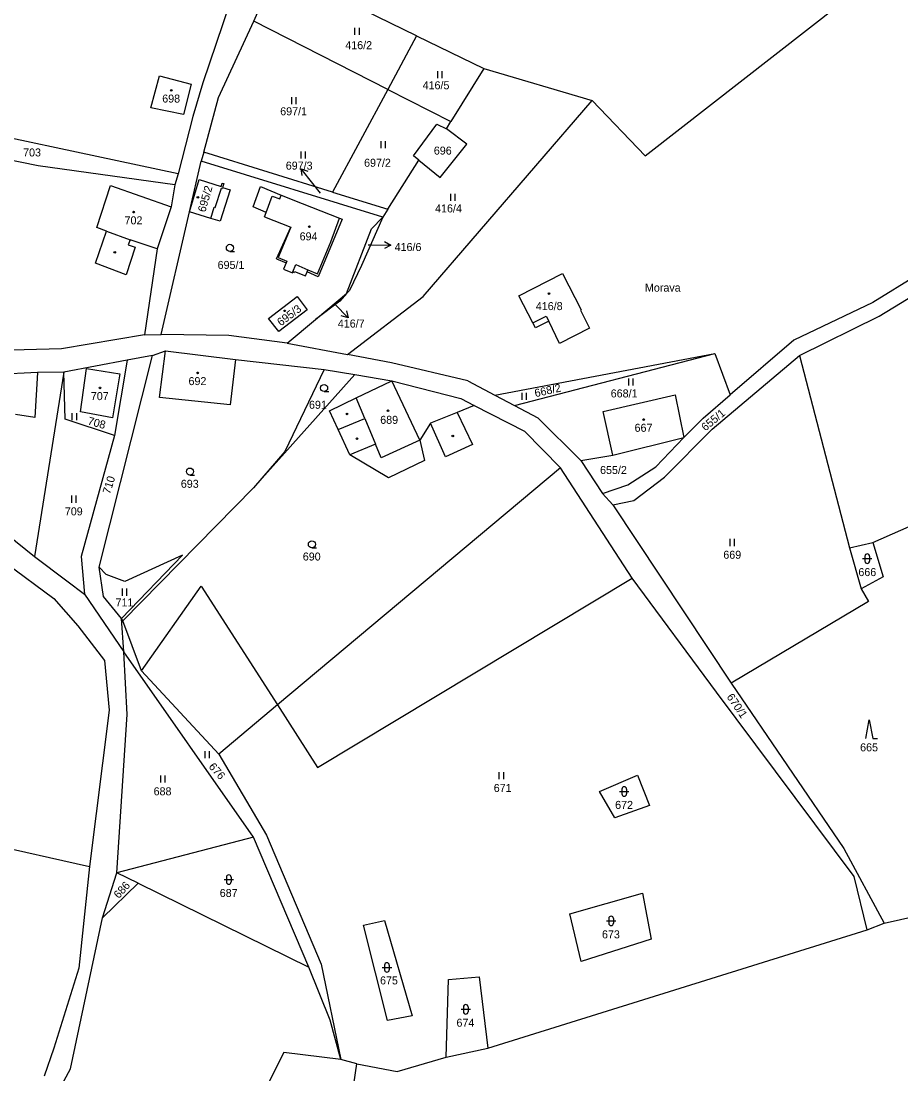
# Model space of a CAD drawing. Extents: x -670359 to -668019, y -978807 to -976674.
# Drawn here: x -668641.1 to -668454.3, y -977825.3 to -977601.7 of the extents above; entities that cross this region are included whole.
import ezdxf

# ---------------------------------------------------------------- set-up
doc = ezdxf.new("R2010")
doc.units = 0
for name, color, linetype in [('Hranice kat_území', 7, 'Continuous'), ('Hranice parcel', 7, 'Continuous'), ('Parcelní čísla', 7, 'Continuous'), ('Pop  PČ popisy', 7, 'Continuous'), ('Vnitřní kresba', 7, 'Continuous'), ('Značky budov', 7, 'Continuous'), ('Značky kultur', 7, 'Continuous')]:
    doc.layers.add(name, color=color, linetype=linetype)

msp = doc.modelspace()

# ---------------------------------------------------------------- linework, layer by layer
at = {"layer": 'Hranice kat_území'}
for points in [[(-668457.87, -977793.35), (-668433.57, -977787.88)], [(-668542.02, -977819.84), (-668461.52, -977794.74)], [(-668461.52, -977794.74), (-668457.87, -977793.35)], [(-668561.25, -977824.85), (-668550.89, -977821.77)], [(-668550.89, -977821.77), (-668542.02, -977819.84)], [(-668572.57, -977841.49), (-668569.84, -977823.18)], [(-668569.84, -977823.18), (-668561.25, -977824.85)]]:
    msp.add_lwpolyline(points, dxfattribs=at)
at = {"layer": 'Hranice parcel'}
for p, q in [((-668557.18, -977604.87), (-668586.71, -977590.44)), ((-668563.3, -977616.26), (-668591.75, -977601.77)), ((-668557.18, -977604.87), (-668563.3, -977616.26)), ((-668557.18, -977604.87), (-668542.9, -977611.84)), ((-668542.9, -977611.84), (-668519.87, -977618.61)), ((-668602.37, -977629.57), (-668599.22, -977618)), ((-668563.3, -977616.26), (-668575, -977638.05)), ((-668563.3, -977616.26), (-668549.89, -977623.09)), ((-668605.37, -977642.22), (-668602.9, -977631.5)), ((-668563.24, -977641.7), (-668556.67, -977631.25)), ((-668605.37, -977642.22), (-668603.32, -977635.42)), ((-668603.32, -977635.42), (-668598.63, -977636.89)), ((-668598.63, -977636.89), (-668598.41, -977636.17)), ((-668598.41, -977636.17), (-668598.11, -977636.26)), ((-668596.76, -977637.56), (-668598.87, -977644.27)), ((-668598.11, -977636.26), (-668598.36, -977637.06)), ((-668598.36, -977637.06), (-668596.76, -977637.56)), ((-668575, -977638.05), (-668563.24, -977641.7)), ((-668585.92, -977638.68), (-668581.45, -977640.5)), ((-668600.87, -977643.66), (-668605.37, -977642.22)), ((-668589.47, -977643.33), (-668589.11, -977642.36)), ((-668598.87, -977644.27), (-668600.87, -977643.66)), ((-668589.47, -977643.33), (-668583.84, -977645.49)), ((-668573.52, -977643.59), (-668572.97, -977643.8)), ((-668586.88, -977652.2), (-668584.86, -977653.08)), ((-668584.86, -977653.08), (-668585.39, -977654.43)), ((-668585.39, -977654.43), (-668583.52, -977655.19)), ((-668583.52, -977655.19), (-668583.44, -977655)), ((-668583.44, -977655), (-668583.18, -977655.11)), ((-668583.18, -977655.11), (-668583.09, -977654.89)), ((-668583.09, -977654.89), (-668580.76, -977655.85)), ((-668580.76, -977655.85), (-668580.41, -977655)), ((-668535.43, -977660.12), (-668526.2, -977655.34)), ((-668526.2, -977655.34), (-668522.22, -977663.1)), ((-668588.63, -977664.88), (-668582.54, -977660.26)), ((-668582.54, -977660.26), (-668580.43, -977663.1)), ((-668532.5, -977665.86), (-668535.43, -977660.12)), ((-668586.44, -977667.7), (-668588.63, -977664.88)), ((-668580.43, -977663.1), (-668586.44, -977667.7)), ((-668522.22, -977663.1), (-668522.33, -977663.17)), ((-668522.33, -977663.17), (-668520.43, -977666.96)), ((-668531.93, -977666.88), (-668532.5, -977665.86)), ((-668529.1, -977665.48), (-668531.93, -977666.88)), ((-668526.78, -977670.2), (-668529.1, -977665.48)), ((-668520.43, -977666.96), (-668526.78, -977670.2)), ((-668536.38, -977683.38), (-668493.85, -977672.35)), ((-668540.55, -977681.17), (-668536.38, -977683.38)), ((-668536.38, -977683.38), (-668531.45, -977686)), ((-668506.35, -977696.41), (-668500.44, -977690.21)), ((-668512.33, -977700.2), (-668506.35, -977696.41)), ((-668517.68, -977702.09), (-668512.33, -977700.2))]:
    msp.add_line(p, q, dxfattribs=at)
for points in [[(-668508.63, -977630.34), (-668419.28, -977560.69)], [(-668589.87, -977577.38), (-668602.57, -977614.87)], [(-668591.75, -977601.77), (-668586.71, -977590.44)], [(-668599.22, -977618), (-668591.75, -977601.77)], [(-668613.61, -977620.19), (-668611.77, -977613.34)], [(-668611.77, -977613.34), (-668605.01, -977615.16)], [(-668542.9, -977611.84), (-668549.89, -977623.09)], [(-668605.01, -977615.16), (-668606.68, -977621.61)], [(-668602.57, -977614.87), (-668604.65, -977622.03)], [(-668606.68, -977621.61), (-668613.61, -977620.19)], [(-668555.76, -977660.24), (-668519.87, -977618.61)], [(-668519.87, -977618.61), (-668508.63, -977630.34)], [(-668607.82, -977634.15), (-668664.97, -977621.98)], [(-668604.65, -977622.03), (-668607.82, -977634.15)], [(-668557.84, -977630.33), (-668552.87, -977623.62)], [(-668552.87, -977623.62), (-668550.83, -977624.66)], [(-668550.83, -977624.66), (-668549.89, -977623.09)], [(-668546.46, -977627.85), (-668550.83, -977624.66)], [(-668637.54, -977632.46), (-668666.42, -977626.62)], [(-668403.78, -977626.71), (-668460.27, -977661.53)], [(-668552.15, -977634.93), (-668546.46, -977627.85)], [(-668602.37, -977629.57), (-668602.9, -977631.5)], [(-668564.3, -977643.39), (-668602.9, -977631.5)], [(-668575, -977638.05), (-668602.37, -977629.57)], [(-668556.67, -977631.25), (-668557.84, -977630.33)], [(-668556.67, -977631.25), (-668552.15, -977634.93)], [(-668458.93, -977664.38), (-668402.04, -977629.73)], [(-668608.5, -977636.5), (-668637.54, -977632.46)], [(-668607.82, -977634.15), (-668608.5, -977636.5)], [(-668625.09, -977645.61), (-668622.18, -977636.66)], [(-668622.18, -977636.66), (-668609.3, -977641.17)], [(-668608.5, -977636.5), (-668609.3, -977641.17)], [(-668591.86, -977641.22), (-668590.3, -977636.9)], [(-668590.3, -977636.9), (-668585.92, -977638.68)], [(-668581.45, -977640.5), (-668573.52, -977643.59)], [(-668609.3, -977641.17), (-668612.22, -977650.13)], [(-668611.39, -977668.3), (-668605.37, -977642.22)], [(-668589.11, -977642.36), (-668591.86, -977641.22)], [(-668563.24, -977641.7), (-668564.3, -977643.39)], [(-668572.97, -977643.8), (-668578.04, -977656.03)], [(-668564.3, -977643.39), (-668568.85, -977653.65), (-668571.43, -977658.96), (-668572.07, -977659.62)], [(-668566.71, -977645.87), (-668564.3, -977643.39)], [(-668625.36, -977653.13), (-668623.01, -977646.34)], [(-668623.01, -977646.34), (-668625.09, -977645.61)], [(-668586.88, -977652.2), (-668583.84, -977645.49)], [(-668572.07, -977659.62), (-668566.71, -977645.87)], [(-668617.98, -977648.19), (-668618.38, -977649.23)], [(-668618.38, -977649.23), (-668616.94, -977649.79)], [(-668612.22, -977650.13), (-668617.98, -977648.19)], [(-668616.94, -977649.79), (-668618.8, -977655.63)], [(-668612.22, -977650.13), (-668614.92, -977668.36)], [(-668618.8, -977655.63), (-668625.36, -977653.13)], [(-668578.04, -977656.03), (-668580.41, -977655)], [(-668572.07, -977659.62), (-668573.45, -977661.25), (-668578.62, -977665.1)], [(-668578.62, -977665.1), (-668572.07, -977659.62)], [(-668571.86, -977672.56), (-668555.76, -977660.24)], [(-668460.27, -977661.53), (-668477.05, -977669.51)], [(-668584.63, -977670.12), (-668578.62, -977665.1)], [(-668475.88, -977672.75), (-668458.93, -977664.38)], [(-668614.92, -977668.36), (-668632.55, -977671.35)], [(-668614.92, -977668.36), (-668611.39, -977668.3)], [(-668597.06, -977668.49), (-668611.39, -977668.3)], [(-668584.63, -977670.12), (-668597.06, -977668.49)], [(-668477.05, -977669.51), (-668490.6, -977681.15)], [(-668632.55, -977671.35), (-668651.2, -977671.86)], [(-668613.23, -977672.8), (-668610.47, -977671.78)], [(-668611.78, -977681.65), (-668610.47, -977671.78)], [(-668610.47, -977671.78), (-668595.64, -977673.58)], [(-668584.63, -977670.12), (-668571.86, -977672.56)], [(-668618.62, -977673.79), (-668632.08, -977676.32)], [(-668624.53, -977717.7), (-668613.23, -977672.8)], [(-668618.62, -977673.79), (-668621.32, -977689.79)], [(-668613.23, -977672.8), (-668618.62, -977673.79)], [(-668595.64, -977673.58), (-668596.78, -977683.22)], [(-668595.64, -977673.58), (-668576.82, -977675.76)], [(-668562.51, -977674.34), (-668571.86, -977672.56)], [(-668540.55, -977681.17), (-668493.85, -977672.35)], [(-668494.37, -977688.42), (-668475.88, -977672.75)], [(-668493.85, -977672.35), (-668490.6, -977681.15)], [(-668475.88, -977672.75), (-668465.23, -977713.62)], [(-668637.69, -977676.34), (-668654.82, -977677.21)], [(-668632.08, -977676.32), (-668638.3, -977715.42)], [(-668637.69, -977676.34), (-668638.2, -977685.9)], [(-668632.08, -977676.32), (-668637.69, -977676.34)], [(-668631.79, -977686.32), (-668632.08, -977676.32)], [(-668628.51, -977684.73), (-668627.27, -977675.53)], [(-668627.27, -977675.53), (-668620.15, -977676.67)], [(-668576.82, -977675.76), (-668585.13, -977693.13)], [(-668576.82, -977675.76), (-668570.3, -977676.8)], [(-668546.31, -977678.11), (-668562.51, -977674.34)], [(-668620.15, -977676.67), (-668621.71, -977686.02)], [(-668570.3, -977676.8), (-668591.8, -977700.84)], [(-668570.3, -977676.8), (-668562.4, -977678.11)], [(-668569.98, -977681.76), (-668562.4, -977678.11)], [(-668562.4, -977678.11), (-668547.8, -977681.9)], [(-668546.31, -977678.11), (-668540.55, -977681.17)], [(-668596.78, -977683.22), (-668611.78, -977681.65)], [(-668575.65, -977684.5), (-668569.98, -977681.76)], [(-668547.8, -977681.9), (-668544.92, -977683.38)], [(-668517.55, -977684.65), (-668502.28, -977681.1)], [(-668502.28, -977681.1), (-668500.44, -977690.21)], [(-668496.29, -977686.04), (-668490.6, -977681.15)], [(-668638.2, -977685.9), (-668642.36, -977685.33)], [(-668621.71, -977686.02), (-668628.51, -977684.73)], [(-668573.82, -977688.51), (-668575.65, -977684.5)], [(-668544.92, -977683.38), (-668548.55, -977684.84)], [(-668548.55, -977684.84), (-668545.26, -977691.68)], [(-668544.92, -977683.38), (-668534.27, -977688.86)], [(-668515.47, -977693.92), (-668517.55, -977684.65)], [(-668621.32, -977689.79), (-668631.79, -977686.32)], [(-668554.23, -977687.12), (-668556.44, -977690.72)], [(-668551.04, -977694.27), (-668554.23, -977687.12)], [(-668531.45, -977686), (-668522.32, -977695.04)], [(-668500.44, -977690.21), (-668496.29, -977686.04)], [(-668621.32, -977689.79), (-668628.41, -977715.46)], [(-668571.37, -977693.88), (-668573.82, -977688.51)], [(-668534.27, -977688.86), (-668526.62, -977696.65)], [(-668504.5, -977698.63), (-668494.37, -977688.42)], [(-668556.44, -977690.72), (-668555.47, -977695.08)], [(-668545.26, -977691.68), (-668551.04, -977694.27)], [(-668515.47, -977693.92), (-668500.44, -977690.21)], [(-668585.13, -977693.13), (-668591.8, -977700.84)], [(-668563.13, -977698.73), (-668571.37, -977693.88)], [(-668522.32, -977695.04), (-668515.47, -977693.92)], [(-668555.47, -977695.08), (-668563.13, -977698.73)], [(-668522.32, -977695.04), (-668517.68, -977702.09)], [(-668659.7, -977698.24), (-668638.3, -977715.42)], [(-668526.62, -977696.65), (-668586.69, -977746.97)], [(-668511.35, -977720.08), (-668526.62, -977696.65)], [(-668511, -977703.53), (-668504.5, -977698.63)], [(-668591.8, -977700.84), (-668619.55, -977729.15)], [(-668517.68, -977702.09), (-668515.52, -977704.49)], [(-668515.52, -977704.49), (-668511, -977703.53)], [(-668515.52, -977704.49), (-668490.35, -977742.35)], [(-668460.3, -977712.51), (-668440.7, -977703.84)], [(-668654.53, -977709.38), (-668634.16, -977724.39)], [(-668465.23, -977713.62), (-668460.3, -977712.51)], [(-668465.23, -977713.62), (-668462.73, -977722.35)], [(-668460.3, -977712.51), (-668458.08, -977719.79)], [(-668638.3, -977715.42), (-668631.43, -977720.64)], [(-668628.41, -977715.46), (-668627.68, -977723.45)], [(-668619.85, -977728.6), (-668606.9, -977715.15)], [(-668606.9, -977715.15), (-668619.09, -977720.77)], [(-668623.67, -977723.94), (-668624.53, -977717.7)], [(-668624.53, -977717.7), (-668623.1, -977719.25)], [(-668631.43, -977720.64), (-668627.68, -977723.45)], [(-668619.09, -977720.77), (-668623.1, -977719.25)], [(-668493.46, -977744.24), (-668511.35, -977720.08)], [(-668458.08, -977719.79), (-668462.73, -977722.35)], [(-668627.68, -977723.45), (-668619.3, -977735.7)], [(-668462.73, -977722.35), (-668461.23, -977725.04)], [(-668634.16, -977724.39), (-668629.06, -977730.17)], [(-668619.85, -977728.6), (-668623.67, -977723.94)], [(-668461.23, -977725.04), (-668490.35, -977742.35)], [(-668619.55, -977729.15), (-668619.85, -977728.6)], [(-668619.3, -977735.7), (-668619.85, -977728.6)], [(-668615.55, -977739.75), (-668619.55, -977729.15)], [(-668629.06, -977730.17), (-668623.4, -977737.55)], [(-668591.77, -977775.03), (-668619.3, -977735.7)], [(-668618.64, -977749.04), (-668619.3, -977735.7)], [(-668623.4, -977737.55), (-668622.47, -977748.11)], [(-668599.16, -977757.41), (-668615.55, -977739.75)], [(-668490.35, -977742.35), (-668466.44, -977777.44)], [(-668464.25, -977783.44), (-668493.46, -977744.24)], [(-668586.69, -977746.97), (-668599.16, -977757.41)], [(-668622.47, -977748.11), (-668626.59, -977781.3)], [(-668620.79, -977782.66), (-668618.64, -977749.04)], [(-668599.16, -977757.41), (-668589.03, -977774.65)], [(-668518.31, -977765.37), (-668510.26, -977761.89)], [(-668510.26, -977761.89), (-668507.68, -977768.31)], [(-668515.06, -977770.93), (-668518.31, -977765.37)], [(-668692.75, -977766.4), (-668626.59, -977781.3)], [(-668507.68, -977768.31), (-668515.06, -977770.93)], [(-668589.03, -977774.65), (-668577.43, -977802.03)], [(-668591.77, -977775.03), (-668620.79, -977782.66)], [(-668580.01, -977802.66), (-668591.77, -977775.03)], [(-668466.44, -977777.44), (-668457.87, -977793.35)], [(-668626.59, -977781.3), (-668628.9, -977802.9)], [(-668623.82, -977792.18), (-668620.79, -977782.66)], [(-668616.3, -977784.86), (-668620.79, -977782.66)], [(-668461.52, -977794.74), (-668464.25, -977783.44)], [(-668623.82, -977792.18), (-668616.3, -977784.86)], [(-668616.3, -977784.86), (-668580.01, -977802.66)], [(-668524.59, -977791.32), (-668509.22, -977786.98)], [(-668509.22, -977786.98), (-668507.32, -977796.73)], [(-668630.67, -977824.25), (-668623.82, -977792.18)], [(-668568.41, -977793.78), (-668563.97, -977792.74)], [(-668563.97, -977792.74), (-668558.11, -977813.03)], [(-668522.23, -977801.49), (-668524.59, -977791.32)], [(-668563.35, -977813.97), (-668568.41, -977793.78)], [(-668507.32, -977796.73), (-668522.23, -977801.49)], [(-668628.9, -977802.9), (-668634.16, -977819.84)], [(-668575.52, -977813.94), (-668580.01, -977802.66)], [(-668577.43, -977802.03), (-668573.26, -977822.26)], [(-668550.89, -977821.77), (-668550.39, -977805.3)], [(-668550.39, -977805.3), (-668543.89, -977804.73)], [(-668543.89, -977804.73), (-668542.02, -977819.84)], [(-668573.26, -977822.26), (-668575.52, -977813.94)], [(-668558.11, -977813.03), (-668563.35, -977813.97)], [(-668634.16, -977819.84), (-668636.27, -977825.84)], [(-668585.38, -977820.8), (-668597.1, -977844.23)], [(-668573.26, -977822.26), (-668585.38, -977820.8)], [(-668569.84, -977823.18), (-668573.26, -977822.26)], [(-668638.79, -977839.27), (-668630.67, -977824.25)]]:
    msp.add_lwpolyline(points, dxfattribs=at)
at = {"layer": 'Parcelní čísla'}
for p, q in [((-668581.44, -977634.57), (-668581.66, -977633.09)), ((-668577.54, -977638.27), (-668579.17, -977636.22)), ((-668567.46, -977649.26), (-668566.65, -977649.27)), ((-668563.94, -977648.54), (-668562.65, -977649.31)), ((-668574.52, -977661.85), (-668574.49, -977661.89)), ((-668572.07, -977663.31), (-668571.71, -977664.76))]:
    msp.add_line(p, q, dxfattribs=at)
for points in [[(-668579.17, -977636.22), (-668581.66, -977633.09), (-668580.26, -977633.64)], [(-668566.65, -977649.27), (-668562.65, -977649.31), (-668563.96, -977650.04)], [(-668574.49, -977661.89), (-668571.71, -977664.76), (-668573.15, -977664.35)]]:
    msp.add_lwpolyline(points, dxfattribs=at)
at = {"layer": 'Vnitřní kresba'}
for p, q in [((-668599.96, -977641.32), (-668598.62, -977637.2)), ((-668598.62, -977637.2), (-668598.43, -977637.27)), ((-668598.43, -977637.27), (-668598.36, -977637.06)), ((-668589.11, -977642.36), (-668587.84, -977638.9)), ((-668587.84, -977638.9), (-668586.23, -977639.49)), ((-668586.23, -977639.49), (-668585.92, -977638.68)), ((-668600.87, -977643.66), (-668600.13, -977641.27)), ((-668600.13, -977641.27), (-668599.96, -977641.32)), ((-668575.37, -977648.62), (-668573.52, -977643.59)), ((-668583.84, -977645.49), (-668586.53, -977651.98)), ((-668578.2, -977655.4), (-668575.37, -977648.62)), ((-668586.53, -977651.98), (-668584.71, -977652.7)), ((-668584.71, -977652.7), (-668584.86, -977653.08)), ((-668583.44, -977655), (-668582.8, -977653.47)), ((-668582.8, -977653.47), (-668580.23, -977654.55)), ((-668580.23, -977654.55), (-668578.2, -977655.4)), ((-668532.5, -977665.86), (-668529.63, -977664.39)), ((-668529.63, -977664.39), (-668529.1, -977665.48))]:
    msp.add_line(p, q, dxfattribs=at)
for points in [[(-668623.01, -977646.34), (-668617.98, -977648.19)], [(-668580.41, -977655), (-668580.23, -977654.55)], [(-668556.44, -977690.72), (-668562.4, -977678.11)], [(-668568.15, -977686.15), (-668569.98, -977681.76)], [(-668548.55, -977684.84), (-668554.23, -977687.12)], [(-668573.82, -977688.51), (-668568.15, -977686.15)], [(-668568.15, -977686.15), (-668565.88, -977691.59)], [(-668565.88, -977691.59), (-668571.37, -977693.88)], [(-668564.66, -977694.52), (-668565.88, -977691.59)], [(-668556.44, -977690.72), (-668564.66, -977694.52)], [(-668578.19, -977760.23), (-668511.35, -977720.08)], [(-668615.55, -977739.75), (-668602.87, -977721.74)], [(-668602.87, -977721.74), (-668586.69, -977746.97)], [(-668586.69, -977746.97), (-668578.19, -977760.23)]]:
    msp.add_lwpolyline(points, dxfattribs=at)
at = {"layer": 'Značky budov'}
for centre in [(-668609.24, -977616.45), (-668603.6, -977639.16), (-668617.24, -977642.31), (-668579.93, -977645.41), (-668529.04, -977659.6), (-668585.16, -977663.28), (-668603.66, -977676.45), (-668624.4, -977679.64), (-668563.23, -977684.51), (-668508.94, -977686.37)]:
    msp.add_circle(centre, 0.175, dxfattribs=at)
at = {"layer": 'Značky kultur'}
for p, q in [((-668570.31, -977603.15), (-668570.31, -977604.65)), ((-668569.31, -977604.65), (-668569.31, -977603.15)), ((-668552.73, -977612.36), (-668552.73, -977613.86)), ((-668551.73, -977613.86), (-668551.73, -977612.36)), ((-668583.74, -977617.88), (-668583.74, -977619.38)), ((-668582.74, -977619.38), (-668582.74, -977617.88)), ((-668564.74, -977627.24), (-668564.74, -977628.74)), ((-668563.74, -977628.74), (-668563.74, -977627.24)), ((-668581.76, -977629.42), (-668581.76, -977630.92)), ((-668580.76, -977630.92), (-668580.76, -977629.42)), ((-668549.95, -977638.41), (-668549.95, -977639.91)), ((-668548.95, -977639.91), (-668548.95, -977638.41)), ((-668596.8, -977650.65), (-668595.8, -977650.65)), ((-668512.15, -977677.66), (-668512.15, -977679.16)), ((-668511.15, -977679.16), (-668511.15, -977677.66)), ((-668576.8, -977680.42), (-668575.8, -977680.42)), ((-668534.8, -977680.66), (-668534.8, -977682.16)), ((-668533.8, -977682.16), (-668533.8, -977680.66)), ((-668630.33, -977685.02), (-668630.33, -977686.52)), ((-668629.33, -977686.52), (-668629.33, -977685.02)), ((-668605.29, -977698.16), (-668604.29, -977698.16)), ((-668630.46, -977702.52), (-668630.46, -977704.02)), ((-668629.46, -977704.02), (-668629.46, -977702.52)), ((-668490.64, -977711.73), (-668490.64, -977713.23)), ((-668489.64, -977713.23), (-668489.64, -977711.73)), ((-668579.39, -977713.61), (-668578.39, -977713.61)), ((-668462.46, -977715.91), (-668460.46, -977715.91)), ((-668461.96, -977715.41), (-668461.96, -977716.41)), ((-668460.96, -977715.41), (-668460.96, -977716.41)), ((-668619.69, -977722.28), (-668619.69, -977723.78)), ((-668618.69, -977723.78), (-668618.69, -977722.28)), ((-668602.14, -977756.79), (-668602.14, -977758.29)), ((-668601.14, -977758.29), (-668601.14, -977756.79)), ((-668539.67, -977761.26), (-668539.67, -977762.76)), ((-668538.67, -977762.76), (-668538.67, -977761.26)), ((-668611.57, -977761.97), (-668611.57, -977763.47)), ((-668610.57, -977763.47), (-668610.57, -977761.97)), ((-668514.07, -977765.36), (-668512.07, -977765.36)), ((-668513.57, -977764.86), (-668513.57, -977765.86)), ((-668512.57, -977764.86), (-668512.57, -977765.86)), ((-668597.53, -977783.56), (-668597.53, -977784.56)), ((-668596.53, -977783.56), (-668596.53, -977784.56)), ((-668598.03, -977784.06), (-668596.03, -977784.06)), ((-668516.36, -977792.35), (-668516.36, -977793.35)), ((-668515.36, -977792.35), (-668515.36, -977793.35)), ((-668516.86, -977792.85), (-668514.86, -977792.85)), ((-668564.45, -977802.72), (-668562.45, -977802.72)), ((-668563.95, -977802.22), (-668563.95, -977803.22)), ((-668562.95, -977802.22), (-668562.95, -977803.22)), ((-668547.73, -977811.62), (-668545.73, -977811.62)), ((-668547.23, -977811.12), (-668547.23, -977812.12)), ((-668546.23, -977811.12), (-668546.23, -977812.12))]:
    msp.add_line(p, q, dxfattribs=at)
msp.add_lwpolyline([(-668461.8, -977754.13), (-668461.05, -977750.13), (-668460.3, -977754.13), (-668459.3, -977754.13)], dxfattribs=at)
for centre, radius in [((-668609.24, -977616.45), 0.175), ((-668603.6, -977639.16), 0.175), ((-668617.24, -977642.31), 0.175), ((-668579.93, -977645.41), 0.175), ((-668596.8, -977649.9), 0.75), ((-668621.25, -977650.85), 0.175), ((-668529.04, -977659.6), 0.175), ((-668585.16, -977663.28), 0.175), ((-668603.66, -977676.45), 0.175), ((-668624.4, -977679.64), 0.175), ((-668576.8, -977679.67), 0.75), ((-668571.92, -977685.18), 0.175), ((-668563.23, -977684.51), 0.175), ((-668508.94, -977686.37), 0.175), ((-668549.48, -977689.86), 0.175), ((-668569.82, -977690.43), 0.175), ((-668605.29, -977697.41), 0.75), ((-668579.39, -977712.86), 0.75)]:
    msp.add_circle(centre, radius, dxfattribs=at)
for centre, start, end in [((-668461.46, -977715.41), 0, 180), ((-668461.46, -977716.41), 180, 0), ((-668513.07, -977764.86), 0, 180), ((-668513.07, -977765.86), 180, 0), ((-668597.03, -977783.56), 0, 180), ((-668597.03, -977784.56), 180, 0), ((-668515.86, -977792.35), 0, 180), ((-668515.86, -977793.35), 180, 0), ((-668563.45, -977802.22), 0, 180), ((-668563.45, -977803.22), 180, 0), ((-668546.73, -977811.12), 0, 180), ((-668546.73, -977812.12), 180, 0)]:
    msp.add_arc(centre, 0.5, start, end, dxfattribs=at)

# ---------------------------------------------------------------- texts
at = {"layer": 'Parcelní čísla'}
for s, height, p in [('416/2', 1.7, (-668572.3, -977607.71)), ('416/5', 1.7, (-668555.88, -977616.23)), ('698', 1.7, (-668611.17, -977619.05)), ('697/1', 1.7, (-668586.12, -977621.75)), ('703', 1.7, (-668640.71, -977630.49)), ('696', 1.7, (-668553.5, -977630.1)), ('697/3', 1.7, (-668584.94, -977633.29)), ('697/2', 1.7, (-668568.31, -977632.68)), ('697/3', 0.1, (-668577.54, -977638.27)), ('416/4', 1.7, (-668553.23, -977642.38)), ('702', 1.7, (-668619.17, -977644.91)), ('694', 1.7, (-668582, -977648.31)), ('416/6', 0.1, (-668567.65, -977649.26)), ('416/6', 1.7, (-668561.82, -977650.57)), ('695/1', 1.7, (-668599.41, -977654.38)), ('416/7', 0.1, (-668574.71, -977661.85)), ('416/8', 1.7, (-668531.84, -977663.12)), ('416/7', 1.7, (-668573.89, -977666.83)), ('692', 1.7, (-668605.59, -977679.05)), ('707', 1.7, (-668626.33, -977682.24)), ('668/1', 1.7, (-668515.94, -977681.67)), ('691', 1.7, (-668580.01, -977684.08)), ('689', 1.7, (-668564.88, -977687.28)), ('667', 1.7, (-668510.87, -977688.97)), ('655/2', 1.7, (-668518.2, -977697.93)), ('693', 1.7, (-668607.22, -977700.86)), ('709', 1.7, (-668631.85, -977706.72)), ('669', 1.7, (-668492.03, -977715.93)), ('690', 1.7, (-668581.32, -977716.31)), ('666', 1.7, (-668463.35, -977719.61)), ('711', 1.7, (-668621.08, -977726.05)), ('665', 1.7, (-668462.98, -977756.83)), ('688', 1.7, (-668613, -977766.17)), ('671', 1.7, (-668540.78, -977765.46)), ('672', 1.7, (-668515, -977769.06)), ('687', 1.7, (-668598.96, -977787.76)), ('673', 1.7, (-668517.79, -977796.55)), ('675', 1.7, (-668564.92, -977806.33)), ('674', 1.7, (-668548.69, -977815.32))]:
    msp.add_text(s, height=height, dxfattribs=at).set_placement(p)
for s, rotation, p in [('695/2', 74, (-668602.03, -977642.45)), ('695/3', 36.8, (-668585.99, -977666.61)), ('668/2', 12.6, (-668531.91, -977681.63)), ('655/1', 39.6, (-668495.84, -977688.91)), ('708', 344.6591, (-668627.12, -977687.39)), ('710', 72.6844, (-668622.26, -977702.31)), ('670/1', 304.1653, (-668491.4, -977745.27)), ('676', 311.6661, (-668601.42, -977760.17)), ('686', 47.6507, (-668620.41, -977788.23))]:
    msp.add_text(s, height=1.7, rotation=rotation, dxfattribs=at).set_placement(p)
at = {"layer": 'Pop  PČ popisy'}
msp.add_text('Morava', height=1.7, dxfattribs=at).set_placement((-668508.67, -977659.2))

doc.saveas('drawing.dxf')
